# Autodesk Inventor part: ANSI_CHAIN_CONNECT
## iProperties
Author: Ole Germer
Shininess: 64.0
Angle Display Precision: 2
Document Length Units: 11272
Document Angle Units: 11286
Document Time Units: 11279
Document Mass Units: 11290
Document Length Units Precision: 3
Document Angle Units Precision: 2
Compacted: True
PropertySet Name: _Private Model Information
Created: 2002-08
Part Number: ANSI_CHAIN_CONNECT
Material: ASTM A36 HRS
Document SubType Name: Modeling
Designer: Ole Germer
Control State: 0
Master: False
Checked Out: False
PropertySet Name: Design Tracking Control
Density: 0.0
Volumn: 0.0
Area: 0.0
PropertySet Name: Model Information
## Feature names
1. Extrusion1
2. Extrusion2
3. Extrusion3
4. Rectangular Pattern1
